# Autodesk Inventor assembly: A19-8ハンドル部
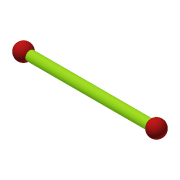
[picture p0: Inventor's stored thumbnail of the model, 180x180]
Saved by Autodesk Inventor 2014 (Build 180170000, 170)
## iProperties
Created: 2008-07
Part Number: A19-8ハンドル部
Document SubType Name: Assembly
Designer: y-shimohigashi
Stock Number: A19-8ハンドル部
Author: y-shimohigashi
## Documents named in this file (3)
- \\SVFL01\Data\技術\CAD\Inventor\テキスト\Inventor_教育Text\R2014（仮）\Inventor2014基礎コース\練習問題-19\A19-8ハンドル部.iam
- \\SVFL01\Data\技術\CAD\Inventor\テキスト\Inventor_教育Text\R2014（仮）\Inventor2014基礎コース\練習問題-19\P19-9ハンドル.ipt
- \\SVFL01\Data\技術\CAD\Inventor\テキスト\Inventor_教育Text\R2014（仮）\Inventor2014基礎コース\練習問題-19\P19-10ボス.ipt
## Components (3 placed, 2 different names)
1. P19-9ハンドル:1 — 挿入:1, 挿入:2
2. P19-10ボス:1 — 挿入:1
3. P19-10ボス:2 — 挿入:2
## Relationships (2: Insert 2)
- 挿入:1 [Insert]: P19-9ハンドル:1 ↔ P19-10ボス:1
- 挿入:2 [Insert]: P19-9ハンドル:1 ↔ P19-10ボス:2
